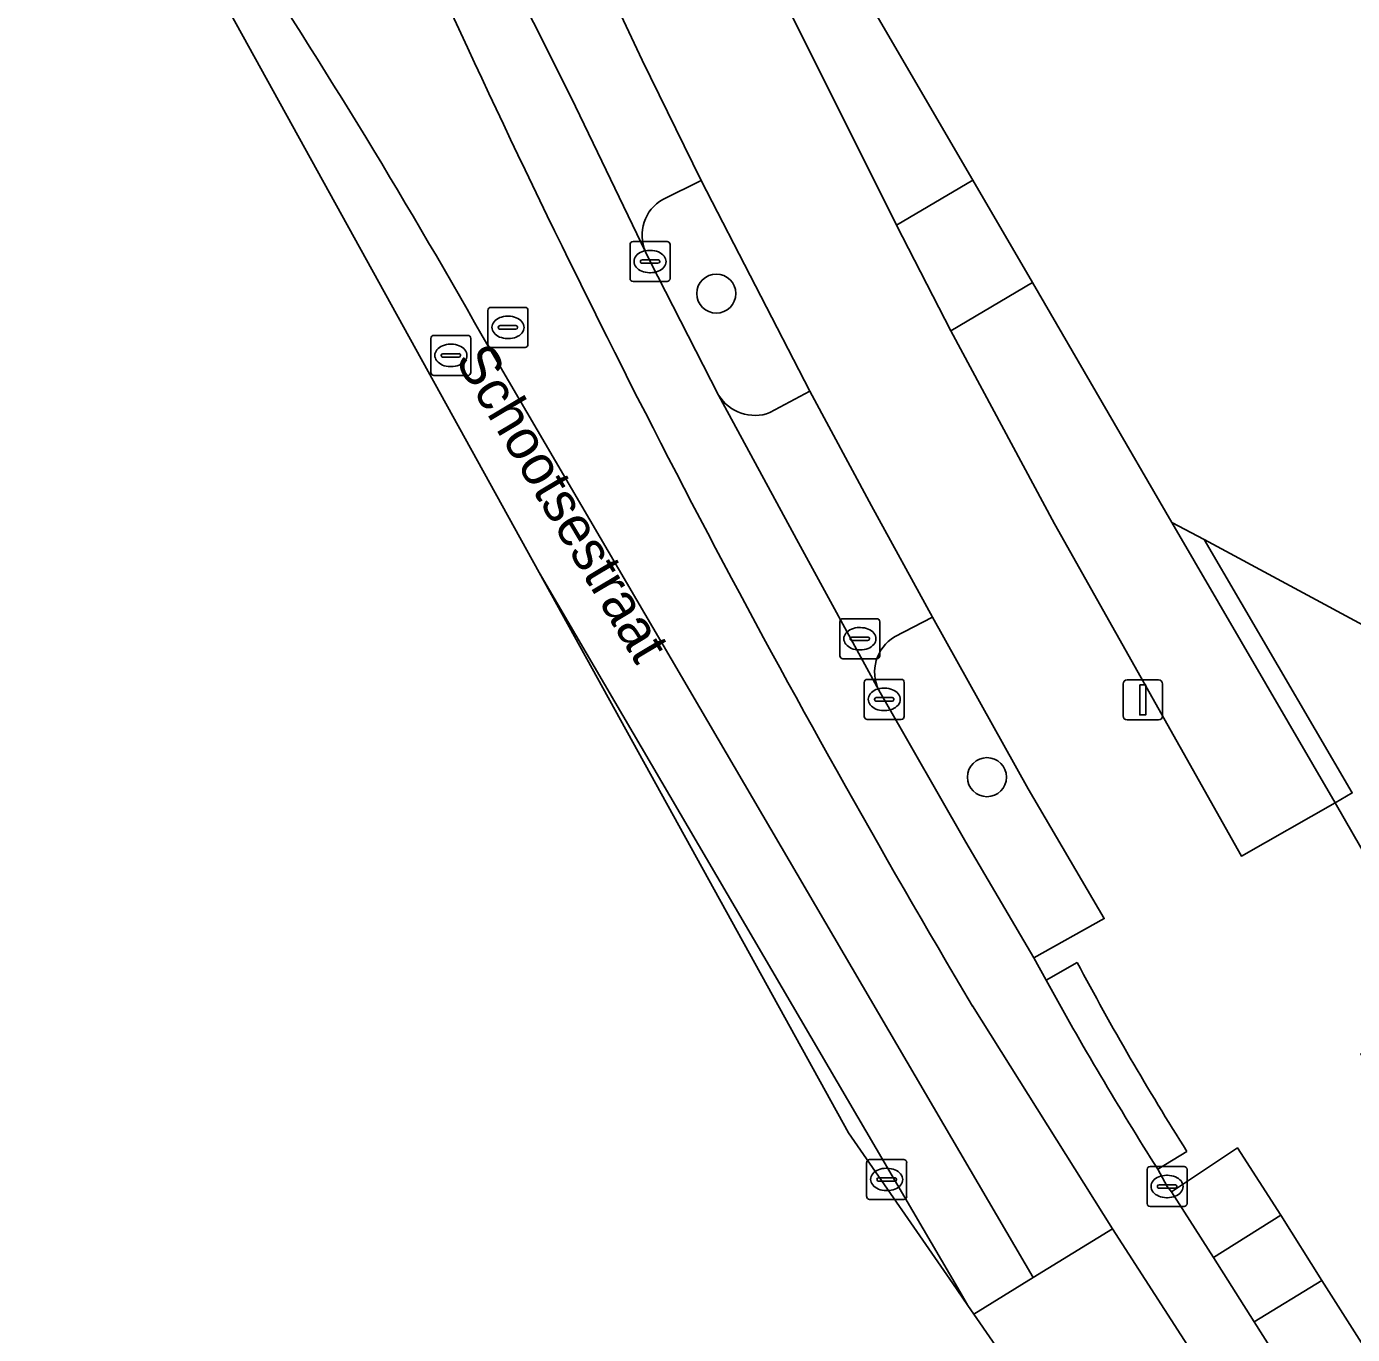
# Model space of a CAD drawing. Extents: x 159489 to 160304, y 383825 to 384531.
# Drawn here: x 159498.76 to 159531.94, y 384258.57 to 384291.29 of the extents above; entities that cross this region are included whole.
import ezdxf

# ---------------------------------------------------------------- set-up
doc = ezdxf.new("R2010")
doc.units = 0
for name, color, linetype in [('IMGEO_Boom', 7, 'Continuous'), ('IMGEO_Erf', 7, 'Continuous'), ('IMGEO_Groenvoorziening', 7, 'Continuous'), ('IMGEO_Kolk', 7, 'Continuous'), ('IMGEO_Lichtmast', 7, 'Continuous'), ('IMGEO_Openbare_ruimte_label', 7, 'Continuous'), ('IMGEO_Pand', 7, 'Continuous'), ('IMGEO_Parkeervlak_open', 7, 'Continuous'), ('IMGEO_Rijbaan_lokaal_gesloten', 7, 'Continuous'), ('IMGEO_Rijbaan_lokaal_open', 7, 'Continuous'), ('IMGEO_Rioolput', 7, 'Continuous'), ('IMGEO_Voetpad_open', 7, 'Continuous')]:
    doc.layers.add(name, color=color, linetype=linetype)

msp = doc.modelspace()

# ---------------------------------------------------------------- linework, layer by layer
at = {"layer": 'IMGEO_Boom'}
for centre in [(159516.018, 384284.612), (159522.79, 384272.513)]:
    msp.add_circle(centre, 0.489, dxfattribs=at)
at = {"layer": 'IMGEO_Erf'}
msp.add_lwpolyline([(159541.03, 384271.564), (159528.221, 384278.456), (159531.931, 384272.12), (159531.499, 384271.869), (159534.333, 384266.954), (159534.768, 384267.2), (159536.603, 384263.927), (159536.735, 384263.691), (159539.953, 384269.688), (159540.015, 384269.655)], close=True, dxfattribs=at)
at = {"layer": 'IMGEO_Groenvoorziening'}
for points in [[(159519.377, 384292.707), (159517.502, 384296.664), (159516.4, 384294.599), (159520.528, 384286.319), (159522.438, 384287.447)], [(159527.419, 384278.887), (159523.926, 384284.889), (159521.885, 384283.676), (159524.479, 384278.85), (159529.156, 384270.537), (159531.499, 384271.869)], [(159528.221, 384278.456), (159527.419, 384278.887), (159531.499, 384271.869), (159531.931, 384272.12)], [(159527.408, 384262.135), (159528.457, 384260.496), (159530.14, 384261.558), (159529.056, 384263.238)], [(159531.17, 384259.924), (159529.475, 384258.882), (159530.676, 384256.993), (159531.995, 384254.871), (159533.67, 384255.984), (159532.339, 384258.083)]]:
    msp.add_lwpolyline(points, close=True, dxfattribs=at)
for points in [[(159515.642, 384287.44), (159514.684, 384286.963)], [(159517.361, 384281.633), (159518.362, 384282.168), (159515.642, 384287.44)], [(159514.249, 384285.66), (159514.361, 384285.413), (159516.075, 384282.074)], [(159520.085, 384274.691), (159520.22, 384274.459), (159522.265, 384270.887), (159523.961, 384267.993), (159525.723, 384268.974), (159523.825, 384272.217), (159521.428, 384276.516)], [(159521.428, 384276.516), (159520.477, 384276.021)]]:
    msp.add_lwpolyline(points, dxfattribs=at)
for centre, radius, start, end in [((159515.17, 384286.077), 1.011, 118.7446, 204.3328), ((159516.982, 384282.622), 1.059, 211.153, 290.9908), ((159521, 384275.144), 1.021, 120.7997, 206.3559)]:
    msp.add_arc(centre, radius, start, end, dxfattribs=at)
at = {"layer": 'IMGEO_Kolk'}
for p, q in [((159513.935, 384285.913), (159514.787, 384285.913)), ((159513.86, 384284.987), (159513.86, 384285.839)), ((159514.348, 384285.693), (159514.373, 384285.693)), ((159514.861, 384285.839), (159514.861, 384284.987)), ((159514.119, 384285.407), (159514.119, 384285.419)), ((159514.557, 384285.37), (159514.159, 384285.37)), ((159514.162, 384285.456), (159514.56, 384285.456)), ((159514.603, 384285.419), (159514.603, 384285.407)), ((159514.787, 384284.913), (159513.935, 384284.913)), ((159514.371, 384285.133), (159514.346, 384285.133)), ((159519.109, 384275.55), (159519.109, 384276.402)), ((159519.184, 384276.476), (159520.036, 384276.476)), ((159519.597, 384276.256), (159519.622, 384276.256)), ((159520.11, 384276.402), (159520.11, 384275.55)), ((159519.368, 384275.97), (159519.368, 384275.982)), ((159519.806, 384275.933), (159519.408, 384275.933)), ((159519.411, 384276.019), (159519.809, 384276.019)), ((159519.852, 384275.982), (159519.852, 384275.97)), ((159519.62, 384275.696), (159519.595, 384275.696)), ((159520.036, 384275.476), (159519.184, 384275.476)), ((159519.794, 384274.959), (159520.646, 384274.959)), ((159519.719, 384274.033), (159519.719, 384274.885)), ((159520.207, 384274.739), (159520.232, 384274.739)), ((159520.72, 384274.885), (159520.72, 384274.033)), ((159519.978, 384274.453), (159519.978, 384274.465)), ((159520.416, 384274.416), (159520.018, 384274.416)), ((159520.021, 384274.502), (159520.419, 384274.502)), ((159520.462, 384274.465), (159520.462, 384274.453)), ((159520.646, 384273.959), (159519.794, 384273.959)), ((159520.23, 384274.179), (159520.205, 384274.179)), ((159519.78, 384262.022), (159519.78, 384262.874)), ((159519.855, 384262.948), (159520.707, 384262.948)), ((159520.268, 384262.728), (159520.293, 384262.728)), ((159520.781, 384262.874), (159520.781, 384262.022)), ((159526.796, 384261.846), (159526.796, 384262.698)), ((159526.871, 384262.772), (159527.723, 384262.772)), ((159527.797, 384262.698), (159527.797, 384261.846)), ((159520.039, 384262.442), (159520.039, 384262.454)), ((159520.477, 384262.405), (159520.079, 384262.405)), ((159520.082, 384262.491), (159520.48, 384262.491)), ((159520.523, 384262.454), (159520.523, 384262.442)), ((159527.284, 384262.552), (159527.309, 384262.552)), ((159520.291, 384262.168), (159520.266, 384262.168)), ((159527.055, 384262.266), (159527.055, 384262.278)), ((159527.493, 384262.229), (159527.095, 384262.229)), ((159527.098, 384262.315), (159527.496, 384262.315)), ((159527.307, 384261.992), (159527.282, 384261.992)), ((159527.539, 384262.278), (159527.539, 384262.266)), ((159520.707, 384261.948), (159519.855, 384261.948)), ((159527.723, 384261.772), (159526.871, 384261.772))]:
    msp.add_line(p, q, dxfattribs=at)
for points in [[(159513.935, 384285.913), (159514.787, 384285.913)], [(159513.86, 384284.987), (159513.86, 384285.839)], [(159514.861, 384285.839), (159514.861, 384284.987)], [(159514.787, 384284.913), (159513.935, 384284.913)], [(159519.109, 384275.55), (159519.109, 384276.402)], [(159519.184, 384276.476), (159520.036, 384276.476)], [(159520.11, 384276.402), (159520.11, 384275.55)], [(159520.036, 384275.476), (159519.184, 384275.476)], [(159519.794, 384274.959), (159520.646, 384274.959)], [(159519.719, 384274.033), (159519.719, 384274.885)], [(159520.72, 384274.885), (159520.72, 384274.033)], [(159520.646, 384273.959), (159519.794, 384273.959)], [(159519.78, 384262.022), (159519.78, 384262.874)], [(159519.855, 384262.948), (159520.707, 384262.948)], [(159520.781, 384262.874), (159520.781, 384262.022)], [(159526.796, 384261.846), (159526.796, 384262.698)], [(159526.871, 384262.772), (159527.723, 384262.772)], [(159527.797, 384262.698), (159527.797, 384261.846)], [(159520.707, 384261.948), (159519.855, 384261.948)], [(159527.723, 384261.772), (159526.871, 384261.772)]]:
    msp.add_lwpolyline(points, dxfattribs=at)
for centre, radius, start, end in [((159513.937, 384285.837), 0.0765, 91.552, 178.448), ((159513.937, 384285.837), 0.0765, 91.552, 178.448), ((159514.785, 384285.837), 0.0765, 1.552, 88.448), ((159514.785, 384285.837), 0.0765, 1.552, 88.448), ((159514.159, 384285.416), 0.0403, 85.8775, 175.7526), ((159514.156, 384285.406), 0.0366, 178.938, 274.7102), ((159514.56, 384285.413), 0.043, 264.8664, 352.4533), ((159514.564, 384285.418), 0.0386, 1.7309, 96.639), ((159513.937, 384284.989), 0.0765, 181.552, 268.448), ((159513.937, 384284.989), 0.0765, 181.552, 268.448), ((159514.785, 384284.989), 0.0765, 271.552, 358.448), ((159514.785, 384284.989), 0.0765, 271.552, 358.448), ((159519.186, 384276.4), 0.0765, 91.552, 178.448), ((159519.186, 384276.4), 0.0765, 91.552, 178.448), ((159520.034, 384276.4), 0.0765, 1.552, 88.448), ((159520.034, 384276.4), 0.0765, 1.552, 88.448), ((159519.408, 384275.979), 0.0403, 85.8775, 175.7526), ((159519.405, 384275.969), 0.0366, 178.938, 274.7102), ((159519.809, 384275.976), 0.043, 264.8664, 352.4533), ((159519.813, 384275.981), 0.0386, 1.7309, 96.639), ((159519.186, 384275.552), 0.0765, 181.552, 268.448), ((159519.186, 384275.552), 0.0765, 181.552, 268.448), ((159520.034, 384275.552), 0.0765, 271.552, 358.448), ((159520.034, 384275.552), 0.0765, 271.552, 358.448), ((159519.796, 384274.883), 0.0765, 91.552, 178.448), ((159519.796, 384274.883), 0.0765, 91.552, 178.448), ((159520.644, 384274.883), 0.0765, 1.552, 88.448), ((159520.644, 384274.883), 0.0765, 1.552, 88.448), ((159520.018, 384274.462), 0.0403, 85.8775, 175.7526), ((159520.015, 384274.452), 0.0366, 178.938, 274.7102), ((159520.419, 384274.459), 0.043, 264.8664, 352.4533), ((159520.423, 384274.464), 0.0386, 1.7309, 96.639), ((159519.796, 384274.035), 0.0765, 181.552, 268.448), ((159519.796, 384274.035), 0.0765, 181.552, 268.448), ((159520.644, 384274.035), 0.0765, 271.552, 358.448), ((159520.644, 384274.035), 0.0765, 271.552, 358.448), ((159519.857, 384262.872), 0.0765, 91.552, 178.448), ((159519.857, 384262.872), 0.0765, 91.552, 178.448), ((159520.705, 384262.872), 0.0765, 1.552, 88.448), ((159520.705, 384262.872), 0.0765, 1.552, 88.448), ((159526.873, 384262.696), 0.0765, 91.552, 178.448), ((159526.873, 384262.696), 0.0765, 91.552, 178.448), ((159527.721, 384262.696), 0.0765, 1.552, 88.448), ((159527.721, 384262.696), 0.0765, 1.552, 88.448), ((159520.079, 384262.451), 0.0403, 85.8775, 175.7526), ((159520.076, 384262.441), 0.0366, 178.938, 274.7102), ((159520.48, 384262.448), 0.043, 264.8664, 352.4533), ((159520.484, 384262.453), 0.0386, 1.7309, 96.639), ((159519.857, 384262.024), 0.0765, 181.552, 268.448), ((159519.857, 384262.024), 0.0765, 181.552, 268.448), ((159520.705, 384262.024), 0.0765, 271.552, 358.448), ((159520.705, 384262.024), 0.0765, 271.552, 358.448), ((159527.095, 384262.275), 0.0403, 85.8775, 175.7526), ((159527.092, 384262.265), 0.0366, 178.938, 274.7102), ((159527.496, 384262.272), 0.043, 264.8664, 352.4533), ((159527.5, 384262.277), 0.0386, 1.7309, 96.639), ((159526.873, 384261.848), 0.0765, 181.552, 268.448), ((159526.873, 384261.848), 0.0765, 181.552, 268.448), ((159527.721, 384261.848), 0.0765, 271.552, 358.448), ((159527.721, 384261.848), 0.0765, 271.552, 358.448)]:
    msp.add_arc(centre, radius, start, end, dxfattribs=at)
for centre, major_axis, ratio, start_param, end_param in [((159514.347, 384285.413), (-0.387, 0.002), 0.722429, 4.712389, 7.853982), ((159514.372, 384285.413), (-0.39, 0.002), 0.717154, 1.570796, 4.712389), ((159519.596, 384275.976), (-0.387, 0.002), 0.722429, 4.712389, 7.853982), ((159519.621, 384275.976), (-0.39, 0.002), 0.717154, 1.570796, 4.712389), ((159520.206, 384274.459), (-0.387, 0.002), 0.722429, 4.712389, 7.853982), ((159520.231, 384274.459), (-0.39, 0.002), 0.717154, 1.570796, 4.712389), ((159520.267, 384262.448), (-0.387, 0.002), 0.722429, 4.712389, 7.853982), ((159520.292, 384262.448), (-0.39, 0.002), 0.717154, 1.570796, 4.712389), ((159527.283, 384262.272), (-0.387, 0.002), 0.722429, 4.712389, 7.853982), ((159527.308, 384262.272), (-0.39, 0.002), 0.717154, 1.570796, 4.712389)]:
    msp.add_ellipse(centre, major_axis=major_axis, ratio=ratio, start_param=start_param, end_param=end_param, dxfattribs=at)
at = {"layer": 'IMGEO_Lichtmast'}
for p, q in [((159526.295, 384274.945), (159527.085, 384274.945)), ((159527.085, 384274.945), (159526.295, 384274.945)), ((159526.195, 384274.045), (159526.195, 384274.845)), ((159526.195, 384274.845), (159526.195, 384274.045)), ((159527.185, 384274.845), (159527.185, 384274.045)), ((159527.185, 384274.045), (159527.185, 384274.845)), ((159527.085, 384273.945), (159526.295, 384273.945)), ((159526.295, 384273.945), (159527.085, 384273.945))]:
    msp.add_line(p, q, dxfattribs=at)
msp.add_lwpolyline([(159526.615, 384274.82), (159526.765, 384274.82), (159526.765, 384274.07), (159526.615, 384274.07), (159526.615, 384274.82)], dxfattribs=at)
for centre, start, end in [((159526.295, 384274.845), 90, 180), ((159526.295, 384274.845), 90, 180), ((159527.085, 384274.845), 0, 90), ((159527.085, 384274.845), 360, 90), ((159526.295, 384274.045), 180, 270), ((159526.295, 384274.045), 180, 270), ((159527.085, 384274.045), 270, 0), ((159527.085, 384274.045), 270, 0)]:
    msp.add_arc(centre, 0.1, start, end, dxfattribs=at)
at = {"layer": 'IMGEO_Pand'}
msp.add_lwpolyline([(159556.766, 384292.015), (159527.484, 384307.756), (159519.695, 384293.297), (159519.377, 384292.707), (159522.438, 384287.447), (159523.926, 384284.889), (159527.419, 384278.887), (159528.221, 384278.456), (159541.03, 384271.564), (159545.068, 384269.391)], close=True, dxfattribs=at)
at = {"layer": 'IMGEO_Parkeervlak_open'}
for points in [[(159510.503, 384293.281), (159512.388, 384289.519), (159514.249, 384285.66)], [(159514.684, 384286.963), (159515.642, 384287.44), (159514.162, 384290.453), (159512.841, 384293.275)], [(159516.075, 384282.074), (159518.077, 384278.372), (159520.085, 384274.691)], [(159518.362, 384282.168), (159517.361, 384281.633)], [(159520.477, 384276.021), (159521.428, 384276.516), (159519.898, 384279.303), (159518.362, 384282.168)], [(159511.588, 384277.632), (159519.324, 384263.618), (159521.935, 384259.842)], [(159522.115, 384259.647), (159511.588, 384277.632)]]:
    msp.add_lwpolyline(points, dxfattribs=at)
for centre, radius, start, end in [((159515.17, 384286.077), 1.011, 118.7446, 204.3328), ((159516.982, 384282.622), 1.059, 211.153, 290.9908), ((159521, 384275.144), 1.021, 120.7997, 206.3559), ((159521.341, 384259.112), 0.94, 34.6502, 50.8947)]:
    msp.add_arc(centre, radius, start, end, dxfattribs=at)
at = {"layer": 'IMGEO_Rijbaan_lokaal_gesloten'}
for points in [[(159524.271, 384267.433), (159523.961, 384267.993), (159522.265, 384270.887), (159520.22, 384274.459), (159520.085, 384274.691), (159518.077, 384278.372), (159516.075, 384282.074), (159514.361, 384285.413), (159514.249, 384285.66), (159512.388, 384289.519), (159510.503, 384293.281), (159509.598, 384295.349), (159509.495, 384295.554), (159506.317, 384302.33), (159505.805, 384303.485), (159505.427, 384304.282), (159505.266, 384304.692), (159500.96, 384314.643), (159500.822, 384314.935), (159499.162, 384314.251), (159499.609, 384313.218), (159504.004, 384303.229), (159509.792, 384290.772)], [(159498.759, 384300.871), (159511.588, 384277.632), (159522.115, 384259.647), (159522.313, 384259.295), (159522.463, 384259.078)], [(159522.463, 384259.078), (159523.948, 384259.997), (159510.16, 384283.557)], [(159522.428, 384266.788), (159525.931, 384261.215), (159538.641, 384241.501), (159554.807, 384217.036)], [(159564.547, 384205.433), (159563.028, 384207.742), (159560.758, 384211.222), (159560.057, 384212.297), (159558.184, 384215.145), (159556.624, 384217.517), (159550.775, 384226.382), (159550.644, 384226.613), (159548.034, 384230.526), (159543.263, 384237.696), (159540.363, 384242.058), (159539.105, 384244.038), (159538.058, 384245.622), (159533.078, 384253.19), (159531.995, 384254.871), (159530.676, 384256.993), (159529.475, 384258.882), (159528.457, 384260.496), (159527.408, 384262.135), (159527.297, 384262.272), (159527.066, 384262.703)]]:
    msp.add_lwpolyline(points, dxfattribs=at)
for centre, radius, start, end in [((159356.003, 384196.45), 177.065, 29.46867, 33.44179), ((159750.363, 384402.196), 265.122, 204.852, 210.71312), ((159600.837, 384309.485), 87.354, 208.77713, 212.38132)]:
    msp.add_arc(centre, radius, start, end, dxfattribs=at)
at = {"layer": 'IMGEO_Rijbaan_lokaal_open'}
for points in [[(159509.792, 384290.772), (159504.004, 384303.229), (159499.609, 384313.218), (159499.162, 384314.251)], [(159510.16, 384283.557), (159523.948, 384259.997), (159525.931, 384261.215), (159522.428, 384266.788)], [(159535.383, 384240.391), (159536.266, 384241.006), (159536.788, 384240.242), (159538.641, 384241.501), (159525.931, 384261.215), (159523.948, 384259.997), (159522.463, 384259.078), (159535.383, 384240.391)]]:
    msp.add_lwpolyline(points, dxfattribs=at)
for centre, radius, start, end in [((159356.003, 384196.45), 177.065, 29.46867, 33.44179), ((159750.363, 384402.196), 265.122, 204.852, 210.71312)]:
    msp.add_arc(centre, radius, start, end, dxfattribs=at)
at = {"layer": 'IMGEO_Rioolput'}
for p, q in [((159510.38, 384284.266), (159511.232, 384284.266)), ((159510.305, 384283.34), (159510.305, 384284.192)), ((159510.793, 384284.046), (159510.818, 384284.046)), ((159511.306, 384284.192), (159511.306, 384283.34)), ((159508.951, 384283.565), (159509.803, 384283.565)), ((159510.564, 384283.76), (159510.564, 384283.772)), ((159511.002, 384283.723), (159510.604, 384283.723)), ((159510.607, 384283.809), (159511.005, 384283.809)), ((159511.048, 384283.772), (159511.048, 384283.76)), ((159508.876, 384282.639), (159508.876, 384283.491)), ((159509.364, 384283.345), (159509.389, 384283.345)), ((159509.877, 384283.491), (159509.877, 384282.639)), ((159511.232, 384283.266), (159510.38, 384283.266)), ((159510.816, 384283.486), (159510.791, 384283.486)), ((159509.135, 384283.059), (159509.135, 384283.071)), ((159509.573, 384283.022), (159509.175, 384283.022)), ((159509.178, 384283.108), (159509.576, 384283.108)), ((159509.619, 384283.071), (159509.619, 384283.059)), ((159509.803, 384282.565), (159508.951, 384282.565)), ((159509.387, 384282.785), (159509.362, 384282.785))]:
    msp.add_line(p, q, dxfattribs=at)
for points in [[(159510.38, 384284.266), (159511.232, 384284.266)], [(159510.305, 384283.34), (159510.305, 384284.192)], [(159511.306, 384284.192), (159511.306, 384283.34)], [(159508.951, 384283.565), (159509.803, 384283.565)], [(159508.876, 384282.639), (159508.876, 384283.491)], [(159509.877, 384283.491), (159509.877, 384282.639)], [(159511.232, 384283.266), (159510.38, 384283.266)], [(159509.803, 384282.565), (159508.951, 384282.565)]]:
    msp.add_lwpolyline(points, dxfattribs=at)
for centre, radius, start, end in [((159510.382, 384284.19), 0.0765, 91.552, 178.448), ((159510.382, 384284.19), 0.0765, 91.552, 178.448), ((159511.23, 384284.19), 0.0765, 1.552, 88.448), ((159511.23, 384284.19), 0.0765, 1.552, 88.448), ((159508.953, 384283.489), 0.0765, 91.552, 178.448), ((159508.953, 384283.489), 0.0765, 91.552, 178.448), ((159509.801, 384283.489), 0.0765, 1.552, 88.448), ((159509.801, 384283.489), 0.0765, 1.552, 88.448), ((159510.604, 384283.769), 0.0403, 85.8775, 175.7526), ((159510.601, 384283.759), 0.0366, 178.938, 274.7102), ((159511.005, 384283.766), 0.043, 264.8664, 352.4533), ((159511.009, 384283.771), 0.0386, 1.7309, 96.639), ((159510.382, 384283.342), 0.0765, 181.552, 268.448), ((159510.382, 384283.342), 0.0765, 181.552, 268.448), ((159511.23, 384283.342), 0.0765, 271.552, 358.448), ((159511.23, 384283.342), 0.0765, 271.552, 358.448), ((159509.175, 384283.068), 0.0403, 85.8775, 175.7526), ((159509.172, 384283.058), 0.0366, 178.938, 274.7102), ((159509.576, 384283.065), 0.043, 264.8664, 352.4533), ((159509.58, 384283.07), 0.0386, 1.7309, 96.639), ((159508.953, 384282.641), 0.0765, 181.552, 268.448), ((159508.953, 384282.641), 0.0765, 181.552, 268.448), ((159509.801, 384282.641), 0.0765, 271.552, 358.448), ((159509.801, 384282.641), 0.0765, 271.552, 358.448)]:
    msp.add_arc(centre, radius, start, end, dxfattribs=at)
for centre, major_axis, ratio, start_param, end_param in [((159510.792, 384283.766), (-0.387, 0.002), 0.722429, 4.712389, 7.853982), ((159510.817, 384283.766), (-0.39, 0.002), 0.717154, 1.570796, 4.712389), ((159509.363, 384283.065), (-0.387, 0.002), 0.722429, 4.712389, 7.853982), ((159509.388, 384283.065), (-0.39, 0.002), 0.717154, 1.570796, 4.712389)]:
    msp.add_ellipse(centre, major_axis=major_axis, ratio=ratio, start_param=start_param, end_param=end_param, dxfattribs=at)
at = {"layer": 'IMGEO_Voetpad_open'}
for points in [[(159506.748, 384302.18), (159508.356, 384302.932), (159510.944, 384297.309), (159512.841, 384293.275), (159514.162, 384290.453), (159515.642, 384287.44), (159518.362, 384282.168), (159519.898, 384279.303), (159521.428, 384276.516), (159523.825, 384272.217), (159525.723, 384268.974), (159523.961, 384267.993), (159524.271, 384267.433), (159525.047, 384267.876)], [(159543.06, 384248.654), (159537.922, 384256.46), (159535.783, 384259.763), (159532.141, 384265.589), (159534.333, 384266.954), (159531.499, 384271.869), (159529.156, 384270.537), (159524.479, 384278.85), (159521.885, 384283.676), (159520.528, 384286.319), (159516.4, 384294.599), (159514.758, 384298.232)], [(159525.047, 384267.876), (159524.271, 384267.433)], [(159527.795, 384263.144), (159527.066, 384262.703), (159527.297, 384262.272), (159527.408, 384262.135), (159529.056, 384263.238), (159530.14, 384261.558), (159531.17, 384259.924), (159532.339, 384258.083), (159533.67, 384255.984), (159534.768, 384254.316), (159538.106, 384249.307), (159539.805, 384246.756), (159538.058, 384245.622), (159539.105, 384244.038), (159540.836, 384245.167), (159541.101, 384245.34), (159546.045, 384237.884), (159553.341, 384226.923), (159558.212, 384219.486), (159567.124, 384205.873)], [(159527.066, 384262.703), (159527.795, 384263.144)], [(159521.935, 384259.842), (159522.313, 384259.295)], [(159522.313, 384259.295), (159522.115, 384259.647)]]:
    msp.add_lwpolyline(points, dxfattribs=at)
for points in [[(159522.438, 384287.447), (159520.528, 384286.319), (159521.885, 384283.676), (159523.926, 384284.889)], [(159530.14, 384261.558), (159528.457, 384260.496), (159529.475, 384258.882), (159531.17, 384259.924)]]:
    msp.add_lwpolyline(points, close=True, dxfattribs=at)
for centre, radius, start, end in [((159589.415, 384302.092), 72.897, 207.99392, 212.29586), ((159589.415, 384302.092), 72.897, 207.99392, 212.29586), ((159600.837, 384309.485), 87.354, 208.77713, 212.38132), ((159521.341, 384259.112), 0.94, 34.6502, 50.8947)]:
    msp.add_arc(centre, radius, start, end, dxfattribs=at)

# ---------------------------------------------------------------- texts
at = {"layer": 'IMGEO_Openbare_ruimte_label'}
msp.add_text('Schootsestraat', height=1, rotation=300.7967, dxfattribs=at).set_placement((159509.465, 384282.956))

doc.saveas('drawing.dxf')
